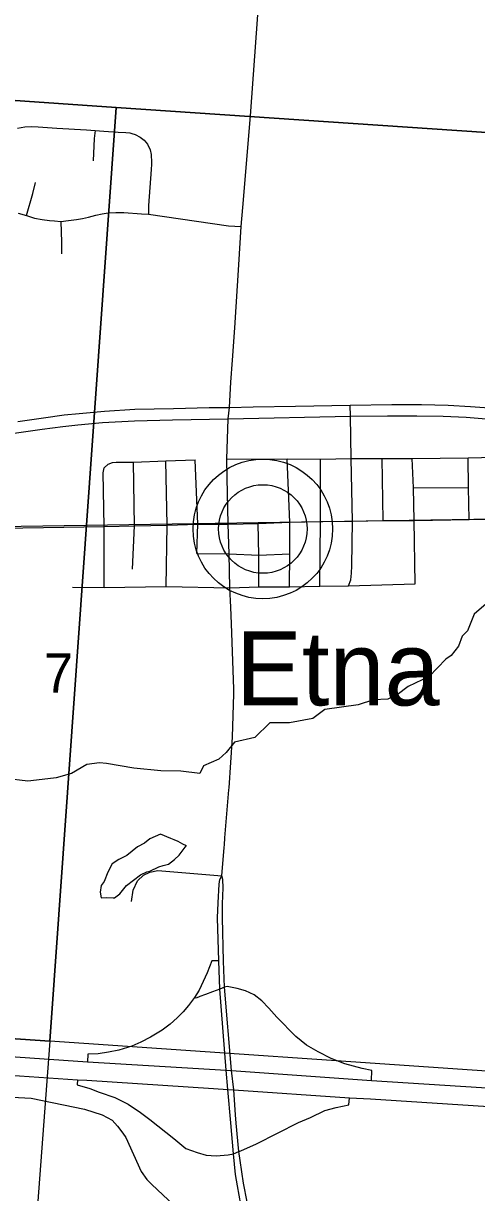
# Model space of a CAD drawing. Extents: x 0 to 34, y 0 to 22.
# Drawn here: x 5.651 to 6.134, y 16.537 to 17.784 of the extents above; entities that cross this region are included whole.
import ezdxf

# ---------------------------------------------------------------- set-up
doc = ezdxf.new("R2010")
doc.units = 0
for name, color, linetype in [('GM_X_Interchange_Ramps', 7, 'Continuous'), ('GM_X_Interstate_Route', 7, 'Continuous'), ('GM_X_Minor_Lake', 7, 'Continuous'), ('GM_X_Minor_River', 7, 'Continuous'), ('GM_X_Rail_Line', 7, 'Continuous'), ('GM_X_Section', 7, 'Continuous'), ('GM_X_Section_Text', 7, 'Continuous'), ('GM_X_State_Route', 7, 'Continuous'), ('GM_X_Township_Road', 7, 'Continuous'), ('GM_X_Unincorporated', 7, 'Continuous'), ('GM_X_Unincorporated_Location', 7, 'Continuous'), ('GM_X_Unincorporated_Text', 7, 'Continuous'), ('GM_X_US_Route', 7, 'Continuous')]:
    doc.layers.add(name, color=color, linetype=linetype)

msp = doc.modelspace()

# ---------------------------------------------------------------- linework, layer by layer
at = {"layer": 'GM_X_Interchange_Ramps'}
for points in [[(5.8596, 16.7844), (5.8522, 16.7845), (5.8473, 16.7718), (5.8386, 16.7534), (5.8337, 16.7456), (5.8274, 16.737), (5.8217, 16.7303), (5.8153, 16.7238), (5.8079, 16.7171), (5.7994, 16.7108), (5.7868, 16.7031), (5.7766, 16.6977), (5.7669, 16.6936), (5.7531, 16.6894), (5.7421, 16.6873), (5.7312, 16.6854), (5.7201, 16.685), (5.7197, 16.6768)], [(5.8656, 16.7566), (5.8607, 16.7545), (5.8529, 16.7515), (5.8454, 16.7488), (5.8395, 16.7465), (5.8354, 16.7446), (5.8337, 16.7456)], [(6.0223, 16.6571), (6.0226, 16.6676), (6.0126, 16.6699), (5.9939, 16.6749), (5.9795, 16.6806), (5.9654, 16.6874), (5.953, 16.6947), (5.9417, 16.7038), (5.9216, 16.7244), (5.9128, 16.7341), (5.9055, 16.7418), (5.8973, 16.7484), (5.888, 16.7527), (5.8791, 16.7552), (5.8685, 16.7571), (5.8656, 16.7566)], [(5.7091, 16.6577), (5.7087, 16.6524), (5.7223, 16.6486), (5.732, 16.6447), (5.7487, 16.6388), (5.7631, 16.6317), (5.7763, 16.623), (5.786, 16.6153)], [(5.8809, 16.5812), (5.8832, 16.5821), (5.8999, 16.5895), (5.9445, 16.6123), (5.9573, 16.6177), (5.9726, 16.6249), (5.9847, 16.6283), (5.9982, 16.6309), (5.9988, 16.6386)], [(5.786, 16.6153), (5.8116, 16.595), (5.8246, 16.5845), (5.8366, 16.5801), (5.8461, 16.5775), (5.857, 16.5768), (5.8695, 16.5776), (5.8754, 16.5789), (5.8809, 16.5812)]]:
    msp.add_lwpolyline(points, dxfattribs=at)
at = {"layer": 'GM_X_Interstate_Route'}
for points in [[(3.3501, 16.8435), (3.6568, 16.822), (3.9185, 16.8032), (4.14, 16.7877), (4.3722, 16.7712), (4.604, 16.7548), (4.6996, 16.7473), (4.8669, 16.7351), (5.1594, 16.714), (5.3993, 16.6976), (5.5708, 16.6871), (5.7197, 16.6768), (5.8676, 16.668), (5.8733, 16.6677), (6.0223, 16.6571), (6.2793, 16.6405), (6.5008, 16.6267), (6.5803, 16.6216)], [(3.3497, 16.8226), (3.6565, 16.8011), (3.9181, 16.7823), (4.1396, 16.7667), (4.3718, 16.7503), (4.6036, 16.7339), (4.693, 16.7276), (4.8604, 16.7157), (5.1529, 16.6946), (5.3928, 16.6782), (5.5644, 16.6677), (5.7091, 16.6577), (5.7188, 16.6572), (5.8539, 16.6483)], [(5.8539, 16.6483), (5.8694, 16.6473), (5.8755, 16.6469), (5.9988, 16.6386), (6.0215, 16.6374), (6.2785, 16.6207), (6.5705, 16.6021)]]:
    msp.add_lwpolyline(points, dxfattribs=at)
at = {"layer": 'GM_X_Minor_Lake'}
for points in [[(5.7976, 16.9195), (5.7862, 16.9146), (5.7806, 16.9101), (5.773, 16.9059), (5.7616, 16.8969), (5.7529, 16.8927), (5.746, 16.8878), (5.7415, 16.8791), (5.7373, 16.8692), (5.7343, 16.865), (5.7331, 16.8578), (5.7342, 16.8517), (5.7395, 16.8521), (5.7471, 16.8517), (5.7486, 16.8517)], [(5.7486, 16.8517), (5.7543, 16.8559), (5.7612, 16.865), (5.7763, 16.8763), (5.7828, 16.8793), (5.7862, 16.8801), (5.7957, 16.8846), (5.8002, 16.8861), (5.8059, 16.8876), (5.8123, 16.8926), (5.8173, 16.8971), (5.8207, 16.9013), (5.8249, 16.907), (5.8252, 16.907), (5.8214, 16.9089), (5.8162, 16.9119), (5.812, 16.9134), (5.8086, 16.915), (5.7976, 16.9195)]]:
    msp.add_lwpolyline(points, dxfattribs=at)
at = {"layer": 'GM_X_Minor_River'}
msp.add_lwpolyline([(6.1446, 17.1651), (6.1317, 17.1542), (6.1249, 17.1363), (6.1192, 17.1307), (6.115, 17.12), (6.1074, 17.1102), (6.1017, 17.106), (6.0839, 17.0875), (6.0615, 17.0769), (6.0497, 17.0682), (6.0399, 17.0636), (6.0247, 17.0629), (6.0081, 17.0573), (5.9728, 17.0524), (5.9599, 17.0429), (5.9349, 17.0381), (5.9141, 17.0381), (5.8982, 17.0226), (5.8762, 17.0177), (5.8675, 17.0067), (5.8595, 16.9995), (5.8432, 16.9923), (5.8394, 16.9844), (5.819, 16.9867), (5.7978, 16.9871), (5.769, 16.9898), (5.7398, 16.9948), (5.7323, 16.9956), (5.719, 16.9937), (5.7027, 16.9843), (5.6864, 16.9798), (5.6773, 16.9787), (5.6561, 16.976), (5.608, 16.9819)], dxfattribs=at)
at = {"layer": 'GM_X_Rail_Line'}
msp.add_lwpolyline([(2.1, 17.1885), (2.293, 17.1932), (3.2433, 17.211), (3.5049, 17.2168), (5.1641, 17.2441), (5.3961, 17.2441), (6.3843, 17.2591), (6.7484, 17.272), (7.243, 17.2836), (8.0477, 17.3015), (8.4974, 17.3184), (8.9, 17.3324)], dxfattribs=at)
at = {"layer": 'GM_X_Section'}
for points in [[(5.2662, 18.2926), (5.3729, 18.2854), (5.6268, 18.2675), (6.2624, 18.2212), (6.2291, 17.6617), (5.7501, 17.6941), (5.2271, 17.7305)], [(5.2271, 17.7305), (5.7501, 17.6941), (5.6796, 16.6989), (5.1577, 16.7346)], [(5.7501, 17.6941), (6.2291, 17.6617), (6.166, 16.6655), (5.6796, 16.6989)], [(5.1577, 16.7346), (5.6796, 16.6989), (5.6042, 15.6994), (5.0919, 15.7328)]]:
    msp.add_lwpolyline(points, close=True, dxfattribs=at)
at = {"layer": 'GM_X_State_Route'}
for p, q in [((5.8662, 16.9155), (5.8704, 16.9668)), ((5.8628, 16.8751), (5.8653, 16.9053))]:
    msp.add_line(p, q, dxfattribs=at)
for points in [[(5.8853, 17.5875), (5.8935, 17.6853), (5.9091, 17.901), (5.9149, 18.0007), (5.9172, 18.0536), (5.9215, 18.1276), (5.9231, 18.1588), (5.9218, 18.1937), (5.9185, 18.2173), (5.9122, 18.2504), (5.9075, 18.2796)], [(5.881, 17.5265), (5.8836, 17.5673), (5.8853, 17.5875)], [(5.8741, 17.4249), (5.8766, 17.4593), (5.881, 17.5265)], [(5.8697, 17.3623), (5.8711, 17.3744), (5.8723, 17.4015), (5.8741, 17.4249)], [(5.8687, 17.2995), (5.8682, 17.3194), (5.8697, 17.3623)], [(5.8724, 17.1614), (5.8715, 17.1822), (5.8708, 17.2184), (5.8697, 17.2499), (5.8687, 17.2995)], [(5.8704, 16.9668), (5.8706, 16.9689), (5.8741, 17.0228), (5.8756, 17.0693), (5.8755, 17.0744), (5.8731, 17.1438), (5.8724, 17.1614)], [(5.8653, 16.9053), (5.8656, 16.9083), (5.8662, 16.9155)], [(5.8754, 16.5789), (5.8724, 16.612), (5.8694, 16.6473), (5.8676, 16.668), (5.8607, 16.7545), (5.8596, 16.7844), (5.8582, 16.8305), (5.8589, 16.8465), (5.86, 16.8664), (5.8608, 16.8714), (5.8628, 16.8751)], [(5.8773, 16.6204), (5.8755, 16.6469), (5.8733, 16.6677), (5.8656, 16.7566), (5.8646, 16.7843), (5.8636, 16.8304), (5.8637, 16.8453), (5.8644, 16.8623), (5.864, 16.8714), (5.8628, 16.8751)], [(5.8809, 16.5812), (5.878, 16.6115), (5.8773, 16.6204)], [(5.8899, 16.5105), (5.8864, 16.515), (5.8831, 16.5248), (5.8795, 16.5448), (5.8776, 16.5569), (5.8754, 16.5789)], [(5.8899, 16.5105), (5.8906, 16.5166), (5.8897, 16.5275), (5.8861, 16.5475), (5.8824, 16.5718), (5.8809, 16.5812)]]:
    msp.add_lwpolyline(points, dxfattribs=at)
at = {"layer": 'GM_X_Township_Road'}
for p, q in [((5.968, 17.2807), (5.9682, 17.3194)), ((6.0347, 17.2538), (6.0338, 17.3202)), ((6.1254, 17.3207), (6.1538, 17.3214)), ((6.0673, 17.2886), (6.1257, 17.2891)), ((5.7373, 17.1825), (5.7376, 17.2468))]:
    msp.add_line(p, q, dxfattribs=at)
for points in [[(5.6451, 17.6723), (5.6527, 17.6734), (5.6596, 17.6738), (5.6669, 17.6734), (5.687, 17.6722), (5.7186, 17.6702), (5.7278, 17.6697), (5.737, 17.669), (5.7525, 17.668), (5.7604, 17.6676), (5.7649, 17.6672), (5.7668, 17.6666), (5.7706, 17.6655), (5.7759, 17.6625), (5.7801, 17.6592), (5.7836, 17.655), (5.7863, 17.6492), (5.7874, 17.6442), (5.7877, 17.6429), (5.788, 17.6365), (5.7879, 17.6338), (5.7876, 17.6281), (5.7848, 17.5898), (5.7847, 17.5805)], [(5.7278, 17.6697), (5.7269, 17.6611), (5.7256, 17.6372)], [(5.6545, 17.579), (5.6614, 17.6024), (5.6644, 17.6141)], [(5.6458, 17.5817), (5.6545, 17.579), (5.6632, 17.5763), (5.6715, 17.5747), (5.6792, 17.5738), (5.6844, 17.5735), (5.6913, 17.5727), (5.6995, 17.5736), (5.7081, 17.5747), (5.7144, 17.5758), (5.7207, 17.5773), (5.7284, 17.5794), (5.7352, 17.581), (5.7416, 17.5818), (5.7426, 17.582), (5.75, 17.5824), (5.7585, 17.5822), (5.7771, 17.581), (5.7847, 17.5805), (5.8698, 17.5681), (5.8836, 17.5673)], [(5.6913, 17.5727), (5.6921, 17.5505), (5.692, 17.5382)], [(6.0014, 17.2867), (6.0007, 17.32), (6.0002, 17.365), (5.9998, 17.377)], [(5.7374, 17.3101), (5.7417, 17.3141), (5.7462, 17.3157), (5.7501, 17.3161), (5.7688, 17.3161), (5.803, 17.3174), (5.8344, 17.3187)], [(5.7678, 17.2021), (5.7699, 17.2481), (5.7688, 17.3161)], [(5.8035, 17.1836), (5.8045, 17.2488), (5.803, 17.3174)], [(5.8361, 17.2186), (5.8374, 17.2499), (5.8344, 17.3187)], [(5.8682, 17.3194), (5.9325, 17.3198), (5.9682, 17.3194), (6.0007, 17.32), (6.0338, 17.3202), (6.0659, 17.32), (6.1254, 17.3207)], [(5.935, 17.1831), (5.9352, 17.2183), (5.9355, 17.252), (5.9325, 17.3198)], [(6.069, 17.1865), (6.068, 17.2541), (6.0673, 17.2886), (6.0659, 17.32)], [(6.1266, 17.255), (6.1257, 17.2891), (6.1254, 17.3207)], [(5.7376, 17.2468), (5.7376, 17.2477), (5.7363, 17.3049), (5.7374, 17.3101)], [(5.9672, 17.1841), (5.9679, 17.2528), (5.968, 17.2807)], [(5.9978, 17.1843), (6.0005, 17.1906), (6.001, 17.1978), (6.0013, 17.2056), (6.002, 17.2534), (6.0014, 17.2867)], [(5.3005, 17.2706), (5.3062, 17.2604), (5.3138, 17.2526), (5.3224, 17.2465), (5.3303, 17.2424), (5.3369, 17.2408), (5.3489, 17.2401), (5.3762, 17.2404), (5.4353, 17.2421), (5.5401, 17.2442), (5.6726, 17.2466), (5.7376, 17.2477), (5.7699, 17.2481), (5.8045, 17.2488), (5.8374, 17.2499), (5.8697, 17.2499), (5.9017, 17.2507), (5.9355, 17.252), (5.9679, 17.2528), (6.002, 17.2534), (6.0347, 17.2538), (6.068, 17.2541), (6.1266, 17.255), (6.2346, 17.257)], [(5.9022, 17.1833), (5.9022, 17.2169), (5.9017, 17.2507)], [(5.8361, 17.2186), (5.8708, 17.2184), (5.9022, 17.2169), (5.9352, 17.2183)], [(5.7035, 17.1829), (5.7373, 17.1825), (5.8035, 17.1836), (5.8715, 17.1822), (5.9022, 17.1833), (5.935, 17.1831), (5.9672, 17.1841), (5.9978, 17.1843), (6.069, 17.1865)], [(5.7666, 16.8478), (5.7682, 16.86), (5.7728, 16.8698), (5.7795, 16.8758), (5.7862, 16.8791), (5.7945, 16.8807), (5.8628, 16.8751)], [(5.1567, 16.672), (5.3341, 16.6553), (5.6597, 16.6381), (5.7163, 16.6266), (5.7354, 16.6205), (5.7461, 16.6148), (5.7517, 16.6083), (5.7574, 16.6007), (5.7604, 16.5964), (5.7768, 16.5599), (5.7828, 16.5516), (5.7881, 16.5461), (5.8118, 16.524), (5.8355, 16.5045), (5.8491, 16.4956), (5.8559, 16.4925), (5.8608, 16.4909), (5.8689, 16.4902), (5.8764, 16.4915), (5.8935, 16.497)]]:
    msp.add_lwpolyline(points, dxfattribs=at)
at = {"layer": 'GM_X_Unincorporated'}
for radius in [0.0744, 0.0472]:
    msp.add_circle((5.9066, 17.2449), radius, dxfattribs=at)
at = {"layer": 'GM_X_Unincorporated_Location'}
msp.add_line((5.9066, 17.2449), (5.9066, 17.2449), dxfattribs=at)
at = {"layer": 'GM_X_US_Route'}
for points in [[(5.6454, 17.3595), (5.6729, 17.3635), (5.6948, 17.3664), (5.7108, 17.368), (5.7377, 17.3704), (5.7702, 17.3725), (5.8115, 17.3735), (5.8495, 17.3743), (5.8711, 17.3744)], [(5.8711, 17.3744), (5.8963, 17.375), (5.9414, 17.3758), (5.9998, 17.377), (6.0441, 17.3777), (6.0758, 17.3777), (6.1041, 17.3768), (6.1281, 17.3756), (6.1577, 17.3733)], [(5.3062, 17.2604), (5.3482, 17.2703), (5.3951, 17.2835), (5.4458, 17.2982), (5.5046, 17.3153), (5.5313, 17.3228), (5.5542, 17.3287), (5.5771, 17.3342), (5.6014, 17.34), (5.644, 17.3474), (5.6715, 17.3514), (5.6934, 17.3543), (5.7094, 17.3559), (5.7355, 17.3585), (5.7699, 17.3602), (5.8101, 17.3613), (5.8697, 17.3623)], [(5.8697, 17.3623), (6.0002, 17.365), (6.0394, 17.3655), (6.0709, 17.3656), (6.0987, 17.3652), (6.1232, 17.3641), (6.1531, 17.3616), (6.1723, 17.3599), (6.1974, 17.3568), (6.2205, 17.3534), (6.2422, 17.35), (6.2579, 17.3471), (6.274, 17.3438), (6.2953, 17.3394), (6.3173, 17.3342), (6.3469, 17.3269), (6.384, 17.3174), (6.4345, 17.3045), (6.4709, 17.2954), (6.502, 17.2885), (6.5251, 17.2841)]]:
    msp.add_lwpolyline(points, dxfattribs=at)

# ---------------------------------------------------------------- texts
at = {"layer": 'GM_X_Section_Text'}
msp.add_text('7', height=0.0419, rotation=0, dxfattribs=at).set_placement((5.6732, 17.0704))
at = {"layer": 'GM_X_Unincorporated_Text'}
msp.add_text('Etna', height=0.07898, rotation=0, dxfattribs=at).set_placement((5.8778, 17.0568))

doc.saveas('drawing.dxf')
